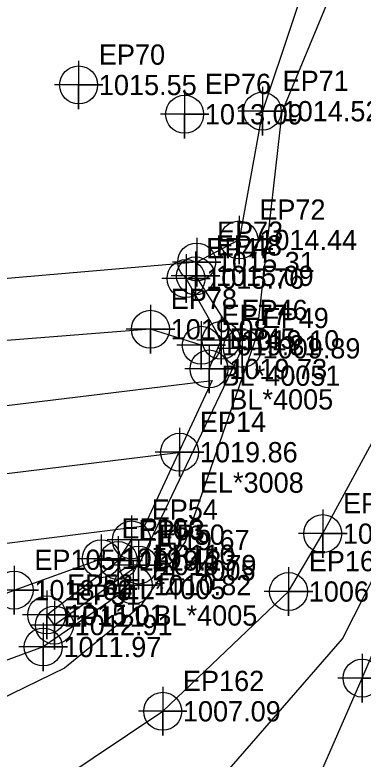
# Model space of a CAD drawing. Extents: x 1382561 to 1383039, y 884068 to 884307.
# Drawn here: x 1382751.3 to 1382794.3, y 884154.1 to 884246 of the extents above; entities that cross this region are included whole.
import ezdxf

# ---------------------------------------------------------------- set-up
doc = ezdxf.new("R2010")
doc.units = 0
for name, color, linetype in [('Exist DTM Breakline', 7, 'Continuous'), ('Exist DTM Breakline Cogo Comment', 7, 'Continuous'), ('Exist DTM Breakline Cogo Elevation', 7, 'Continuous'), ('Exist DTM Breakline Cogo Number', 7, 'Continuous'), ('Exist DTM Breakline Cogo Point CELL', 7, 'Continuous'), ('Exist DTM Breakline Underwater', 7, 'Continuous'), ('Exist DTM Breakline Underwater Cogo Elevation', 7, 'Continuous'), ('Exist DTM Breakline Underwater Cogo Number', 7, 'Continuous'), ('Exist DTM Breakline Underwater Cogo Point CELL', 7, 'Continuous'), ('Exist DTM Crownline', 7, 'Continuous'), ('Exist DTM Crownline Cogo Comment', 7, 'Continuous'), ('Exist DTM Crownline Cogo Elevation', 7, 'Continuous'), ('Exist DTM Crownline Cogo Number', 7, 'Continuous'), ('Exist DTM Crownline Cogo Point CELL', 7, 'Continuous'), ('Exist DTM Regular Point CELL', 7, 'Continuous'), ('Exist DTM Regular Point Cogo Elevation', 7, 'Continuous'), ('Exist DTM Regular Point Cogo Number', 7, 'Continuous'), ('Exist Hydro Stream or Body of Water', 7, 'Continuous'), ('Exist Roads EOP', 7, 'Continuous')]:
    doc.layers.add(name, color=color, linetype=linetype)

msp = doc.modelspace()

# ---------------------------------------------------------------- linework, layer by layer
at = {"layer": 'Exist DTM Breakline'}
for points in [[(1382806.7045, 884288.1336), (1382793.0575, 884267.4591), (1382781.8725, 884234.0918), (1382778.997, 884218.196), (1382773.7671, 884215.476), (1382722.2214, 884211.0337), (1382668.872, 884203.9756), (1382615.627, 884202.5184), (1382567.5113, 884196.1242)], [(1382775.2939, 884202.276), (1382776.7928, 884205.8148), (1382772.4489, 884213.4303), (1382773.6251, 884213.7705), (1382779.4009, 884204.8221), (1382766.5629, 884178.0817), (1382756.1938, 884170.6745), (1382755.2433, 884171.9236), (1382764.08, 884178.6419), (1382765.7075, 884181.1752)], [(1382774.3329, 884205.1982), (1382768.0574, 884207.1773), (1382721.0722, 884203.493), (1382670.0814, 884197.4905), (1382619.8383, 884190.0037), (1382569.9863, 884185.1279)], [(1382751.4287, 884075.9856), (1382771.8716, 884111.3375), (1382784.8942, 884142.8663), (1382794.19, 884164.1279), (1382801.7626, 884181.793), (1382802.1903, 884175.7622), (1382803.9822, 884162.9447), (1382834.7331, 884146.1448), (1382885.2227, 884156.817), (1382912.2708, 884159.0791), (1382962.484, 884168.5252), (1383014.0488, 884181.852)], [(1382574.4485, 884150.6451), (1382626.0018, 884158.34), (1382674.2791, 884163.6957), (1382717.959, 884168.385), (1382736.7551, 884169.3534), (1382751.216, 884174.9855), (1382761.9845, 884178.8637)], [(1382765.9243, 884175.6081), (1382754.8134, 884167.9678), (1382731.7194, 884159.5309), (1382722.2333, 884160.3495), (1382705.5702, 884145.487), (1382682.8713, 884116.2267), (1382674.3334, 884104.2092), (1382674.6208, 884111.7647), (1382664.0032, 884106.0759), (1382669.8487, 884092.884)]]:
    msp.add_lwpolyline(points, dxfattribs=at)
at = {"layer": 'Exist DTM Breakline Cogo Point CELL'}
for points in [[(1382781.8725, 884237.0918), (1382781.8725, 884231.0918), (1382781.8725, 884234.0918), (1382784.8725, 884234.0918), (1382778.8725, 884234.0918)], [(1382778.997, 884221.196), (1382778.997, 884215.196), (1382778.997, 884218.196), (1382781.997, 884218.196), (1382775.997, 884218.196)], [(1382773.7671, 884218.476), (1382773.7671, 884212.476), (1382773.7671, 884215.476), (1382776.7671, 884215.476), (1382770.7671, 884215.476)], [(1382772.4489, 884216.4303), (1382772.4489, 884210.4303), (1382772.4489, 884213.4303), (1382775.4489, 884213.4303), (1382769.4489, 884213.4303)], [(1382773.6251, 884216.7705), (1382773.6251, 884210.7705), (1382773.6251, 884213.7705), (1382776.6251, 884213.7705), (1382770.6251, 884213.7705)], [(1382768.0574, 884210.1773), (1382768.0574, 884204.1773), (1382768.0574, 884207.1773), (1382771.0574, 884207.1773), (1382765.0574, 884207.1773)], [(1382776.7928, 884208.8148), (1382776.7928, 884202.8148), (1382776.7928, 884205.8148), (1382779.7928, 884205.8148), (1382773.7928, 884205.8148)], [(1382774.3329, 884208.1982), (1382774.3329, 884202.1982), (1382774.3329, 884205.1982), (1382777.3329, 884205.1982), (1382771.3329, 884205.1982)], [(1382779.4009, 884207.8221), (1382779.4009, 884201.8221), (1382779.4009, 884204.8221), (1382782.4009, 884204.8221), (1382776.4009, 884204.8221)], [(1382775.2939, 884205.276), (1382775.2939, 884199.276), (1382775.2939, 884202.276), (1382778.2939, 884202.276), (1382772.2939, 884202.276)], [(1382765.7075, 884184.1752), (1382765.7075, 884178.1752), (1382765.7075, 884181.1752), (1382768.7075, 884181.1752), (1382762.7075, 884181.1752)], [(1382761.9845, 884181.8637), (1382761.9845, 884175.8637), (1382761.9845, 884178.8637), (1382764.9845, 884178.8637), (1382758.9845, 884178.8637)], [(1382764.08, 884181.6419), (1382764.08, 884175.6419), (1382764.08, 884178.6419), (1382767.08, 884178.6419), (1382761.08, 884178.6419)], [(1382766.5629, 884181.0817), (1382766.5629, 884175.0817), (1382766.5629, 884178.0817), (1382769.5629, 884178.0817), (1382763.5629, 884178.0817)], [(1382765.9243, 884178.6081), (1382765.9243, 884172.6081), (1382765.9243, 884175.6081), (1382768.9243, 884175.6081), (1382762.9243, 884175.6081)], [(1382751.216, 884177.9855), (1382751.216, 884171.9855), (1382751.216, 884174.9855), (1382754.216, 884174.9855), (1382748.216, 884174.9855)], [(1382755.2433, 884174.9236), (1382755.2433, 884168.9236), (1382755.2433, 884171.9236), (1382758.2433, 884171.9236), (1382752.2433, 884171.9236)], [(1382756.1938, 884173.6745), (1382756.1938, 884167.6745), (1382756.1938, 884170.6745), (1382759.1938, 884170.6745), (1382753.1938, 884170.6745)], [(1382754.8134, 884170.9678), (1382754.8134, 884164.9678), (1382754.8134, 884167.9678), (1382757.8134, 884167.9678), (1382751.8134, 884167.9678)], [(1382794.19, 884167.1279), (1382794.19, 884161.1279), (1382794.19, 884164.1279), (1382797.19, 884164.1279), (1382791.19, 884164.1279)]]:
    msp.add_lwpolyline(points, dxfattribs=at)
for centre in [(1382781.8725, 884234.0918), (1382778.997, 884218.196), (1382773.7671, 884215.476), (1382773.6251, 884213.7705), (1382772.4489, 884213.4303), (1382768.0574, 884207.1773), (1382776.7928, 884205.8148), (1382774.3329, 884205.1982), (1382779.4009, 884204.8221), (1382775.2939, 884202.276), (1382765.7075, 884181.1752), (1382761.9845, 884178.8637), (1382764.08, 884178.6419), (1382766.5629, 884178.0817), (1382765.9243, 884175.6081), (1382751.216, 884174.9855), (1382755.2433, 884171.9236), (1382756.1938, 884170.6745), (1382754.8134, 884167.9678), (1382794.19, 884164.1279)]:
    msp.add_circle(centre, 2.344, dxfattribs=at)
at = {"layer": 'Exist DTM Breakline Underwater'}
msp.add_lwpolyline([(1382688.3783, 884086.9383), (1382699.504, 884112.5821), (1382721.2073, 884133.5617), (1382743.6214, 884142.6712), (1382769.5658, 884160.0329), (1382785.1067, 884174.8132), (1382789.3291, 884181.9565), (1382809.982, 884219.9732), (1382816.0046, 884242.1273), (1382837.3981, 884258.7844), (1382845.6113, 884276.5289)], dxfattribs=at)
at = {"layer": 'Exist DTM Breakline Underwater Cogo Point CELL'}
for points in [[(1382789.3291, 884184.9565), (1382789.3291, 884178.9565), (1382789.3291, 884181.9565), (1382792.3291, 884181.9565), (1382786.3291, 884181.9565)], [(1382785.1067, 884177.8132), (1382785.1067, 884171.8132), (1382785.1067, 884174.8132), (1382788.1067, 884174.8132), (1382782.1067, 884174.8132)], [(1382769.5658, 884163.0329), (1382769.5658, 884157.0329), (1382769.5658, 884160.0329), (1382772.5658, 884160.0329), (1382766.5658, 884160.0329)]]:
    msp.add_lwpolyline(points, dxfattribs=at)
for centre in [(1382789.3291, 884181.9565), (1382785.1067, 884174.8132), (1382769.5658, 884160.0329)]:
    msp.add_circle(centre, 2.344, dxfattribs=at)
at = {"layer": 'Exist DTM Crownline'}
msp.add_lwpolyline([(1382573.1626, 884167.9166), (1382622.8682, 884173.7315), (1382672.5741, 884179.7354), (1382722.0434, 884185.9092), (1382771.4612, 884191.9829)], dxfattribs=at)
at = {"layer": 'Exist DTM Crownline Cogo Point CELL'}
msp.add_lwpolyline([(1382771.6575, 884195.007), (1382771.6575, 884189.007), (1382771.6575, 884192.007), (1382774.6575, 884192.007), (1382768.6575, 884192.007)], dxfattribs=at)
msp.add_circle((1382771.6575, 884192.007), 2.344, dxfattribs=at)
at = {"layer": 'Exist DTM Regular Point CELL'}
for points in [[(1382759.1849, 884240.3247), (1382759.1849, 884234.3247), (1382759.1849, 884237.3247), (1382762.1849, 884237.3247), (1382756.1849, 884237.3247)], [(1382772.2774, 884236.7124), (1382772.2774, 884230.7124), (1382772.2774, 884233.7124), (1382775.2774, 884233.7124), (1382769.2774, 884233.7124)]]:
    msp.add_lwpolyline(points, dxfattribs=at)
for centre in [(1382759.1849, 884237.3247), (1382772.2774, 884233.7124)]:
    msp.add_circle(centre, 2.344, dxfattribs=at)
at = {"layer": 'Exist Hydro Stream or Body of Water'}
for points in [[(1382815.7469, 884285.0295), (1382796.5538, 884263.5381), (1382784.2894, 884233.9786), (1382781.1386, 884206.3096), (1382772.3397, 884180.9543), (1382766.7799, 884172.9781), (1382757.421, 884165.3571), (1382736.1951, 884155.0402), (1382706.3401, 884136.6072), (1382689.3837, 884112.6314), (1382676.096, 884092.4493)], [(1382697.0874, 884084.7019), (1382707.0296, 884107.5273), (1382718.101, 884120.6229), (1382747.1797, 884135.9958), (1382776.4132, 884151.3238), (1382791.7634, 884168.9711), (1382798.6691, 884182.5745), (1382820.5432, 884217.5751), (1382820.037, 884238.4145), (1382839.3094, 884257.7694), (1382850.1603, 884274.5827)]]:
    msp.add_lwpolyline(points, dxfattribs=at)
at = {"layer": 'Exist Roads EOP'}
for points in [[(1382572.4495, 884176.8659), (1382622.0271, 884182.499), (1382672.5956, 884188.515), (1382721.14, 884194.2421), (1382775.6714, 884200.8541)], [(1382775.6714, 884200.8541), (1382767.3133, 884182.9042)], [(1382574.0878, 884158.9549), (1382623.8158, 884164.9302), (1382674.5802, 884171.138), (1382723.4333, 884177.3901), (1382767.3133, 884182.9042)]]:
    msp.add_lwpolyline(points, dxfattribs=at)

# ---------------------------------------------------------------- texts
at = {"layer": 'Exist DTM Breakline Cogo Comment'}
for s, p in [('BL*40051', (1382776.8329, 884200.1982)), ('BL*4005', (1382777.7939, 884197.276)), ('EL*4005', (1382768.2075, 884176.1752)), ('EL*4005', (1382764.4845, 884173.8637)), ('BL*4005', (1382768.4243, 884170.6081))]:
    msp.add_text(s, height=2.5, dxfattribs=at).set_placement(p)
at = {"layer": 'Exist DTM Breakline Cogo Elevation'}
for s, p in [('1014.52', (1382784.3725, 884232.8418)), ('1014.44', (1382781.497, 884216.946)), ('1015.31', (1382776.2671, 884214.226)), ('1015.76', (1382774.9489, 884212.1803)), ('1015.09', (1382776.1251, 884212.5205)), ('1019.08', (1382770.5574, 884205.9273)), ('1019.10', (1382779.2928, 884204.5648)), ('1019.31', (1382776.8329, 884203.9482)), ('1009.89', (1382781.9009, 884203.5721)), ('1019.73', (1382777.7939, 884201.026)), ('1019.67', (1382768.2075, 884179.9252)), ('1019.45', (1382764.4845, 884177.6137)), ('1019.23', (1382766.58, 884177.3919)), ('1010.79', (1382769.0629, 884176.8317)), ('1010.82', (1382768.4243, 884174.3581)), ('1018.60', (1382753.716, 884173.7355)), ('1015.01', (1382757.7433, 884170.6736)), ('1012.91', (1382758.6938, 884169.4245)), ('1011.97', (1382757.3134, 884166.7178))]:
    msp.add_text(s, height=2.5, dxfattribs=at).set_placement(p)
at = {"layer": 'Exist DTM Breakline Cogo Number'}
for s, p in [('EP71', (1382784.3725, 884236.5918)), ('EP72', (1382781.497, 884220.696)), ('EP73', (1382776.2671, 884217.976)), ('EP47', (1382774.9489, 884215.9303)), ('EP48', (1382776.1251, 884216.2705)), ('EP78', (1382770.5574, 884209.6773)), ('EP46', (1382779.2928, 884208.3148)), ('EP77', (1382776.8329, 884207.6982)), ('EP49', (1382781.9009, 884207.3221)), ('EP45', (1382777.7939, 884204.776)), ('EP54', (1382768.2075, 884183.6752)), ('EP106', (1382764.4845, 884181.3637)), ('EP53', (1382766.58, 884181.1419)), ('EP50', (1382769.0629, 884180.5817)), ('EP110', (1382768.4243, 884178.1081)), ('EP105', (1382753.716, 884177.4855)), ('EP52', (1382757.7433, 884174.4236)), ('EP51', (1382758.6938, 884173.1745)), ('EP111', (1382757.3134, 884170.4678))]:
    msp.add_text(s, height=2.5, dxfattribs=at).set_placement(p)
at = {"layer": 'Exist DTM Breakline Underwater Cogo Elevation'}
for s, p in [('1007.87', (1382791.8291, 884180.7065)), ('1006.95', (1382787.6067, 884173.5632)), ('1007.09', (1382772.0658, 884158.7829))]:
    msp.add_text(s, height=2.5, dxfattribs=at).set_placement(p)
at = {"layer": 'Exist DTM Breakline Underwater Cogo Number'}
for s, p in [('EP168', (1382791.8291, 884184.4565)), ('EP167', (1382787.6067, 884177.3132)), ('EP162', (1382772.0658, 884162.5329))]:
    msp.add_text(s, height=2.5, dxfattribs=at).set_placement(p)
at = {"layer": 'Exist DTM Crownline Cogo Comment'}
msp.add_text('EL*3008', height=2.5, dxfattribs=at).set_placement((1382774.1575, 884187.007))
at = {"layer": 'Exist DTM Crownline Cogo Elevation'}
msp.add_text('1019.86', height=2.5, dxfattribs=at).set_placement((1382774.1575, 884190.757))
at = {"layer": 'Exist DTM Crownline Cogo Number'}
msp.add_text('EP14', height=2.5, dxfattribs=at).set_placement((1382774.1575, 884194.507))
at = {"layer": 'Exist DTM Regular Point Cogo Elevation'}
for s, p in [('1015.55', (1382761.6849, 884236.0747)), ('1013.09', (1382774.7774, 884232.4624))]:
    msp.add_text(s, height=2.5, dxfattribs=at).set_placement(p)
at = {"layer": 'Exist DTM Regular Point Cogo Number'}
for s, p in [('EP70', (1382761.6849, 884239.8247)), ('EP76', (1382774.7774, 884236.2124))]:
    msp.add_text(s, height=2.5, dxfattribs=at).set_placement(p)

doc.saveas('drawing.dxf')
